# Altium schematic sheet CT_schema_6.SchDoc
size 371 x 336 mm
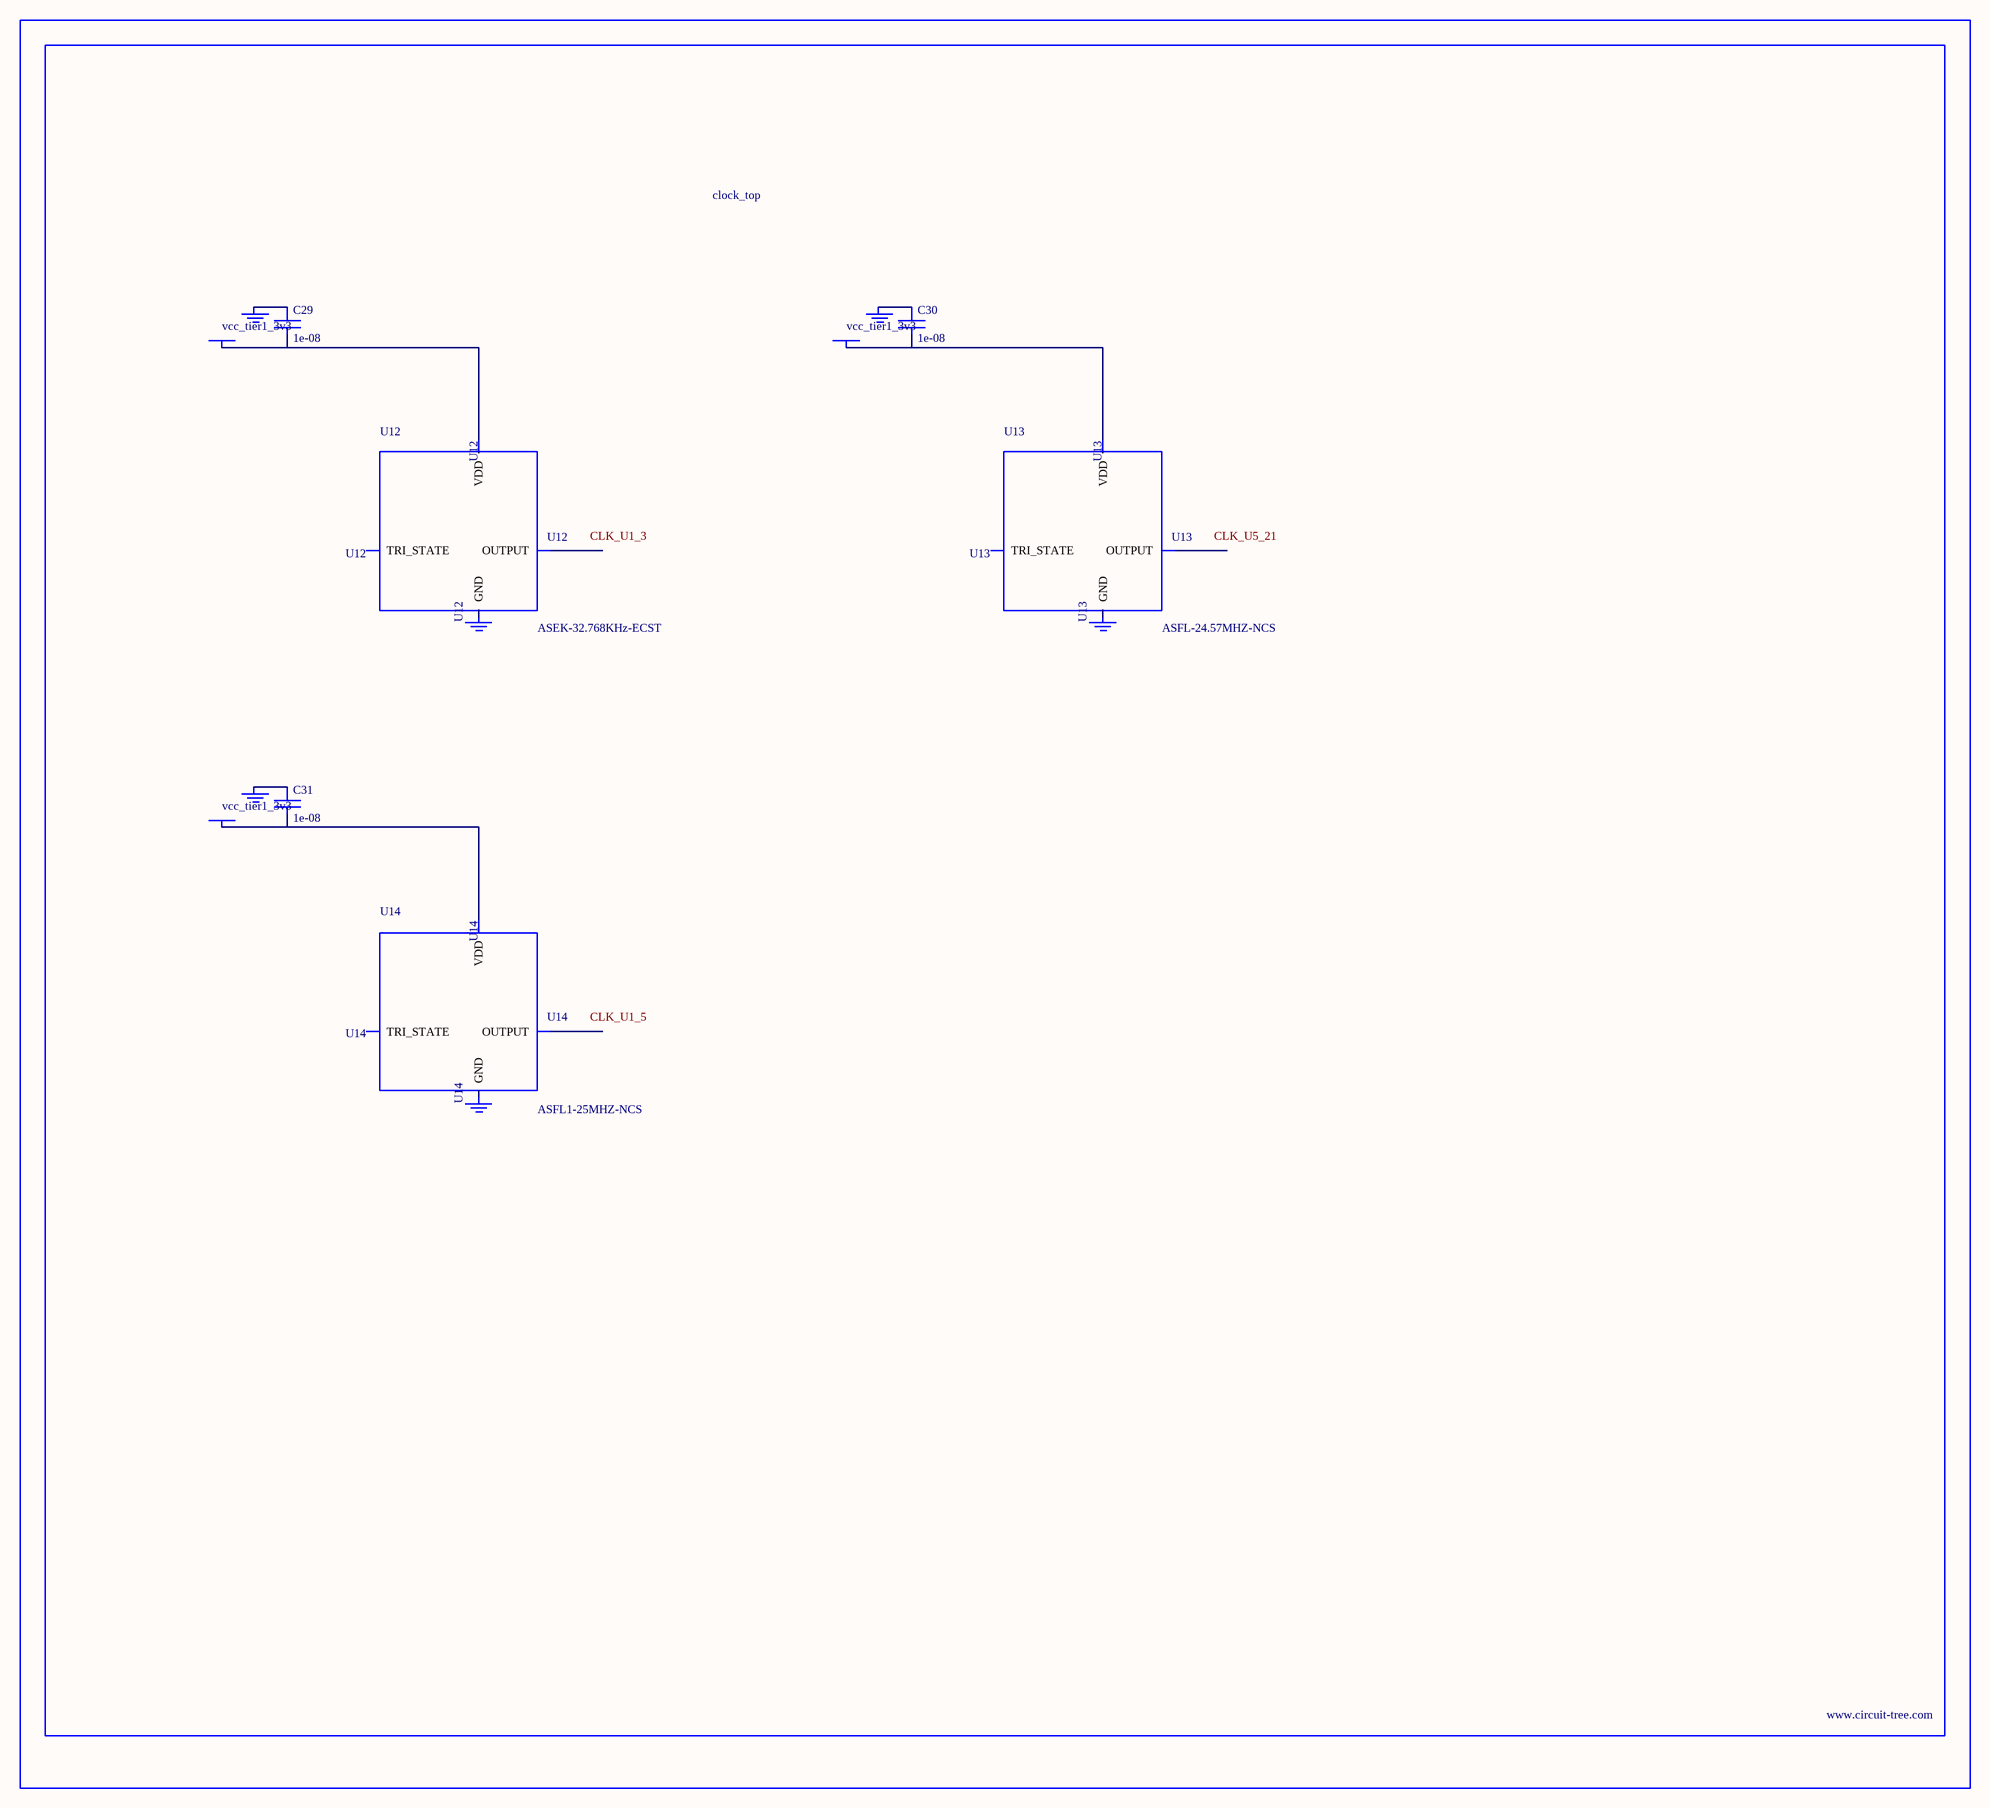
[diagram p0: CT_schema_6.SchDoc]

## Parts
BORDER5  (no value)
C29  1e-08  [C0402]
C30  1e-08  [C0402]
C31  1e-08  [C0402]
GND_INSTANCE_5_0  (no value)
GND_INSTANCE_5_1  (no value)
GND_INSTANCE_5_2  (no value)
GND_INSTANCE_5_3  (no value)
GND_INSTANCE_5_4  (no value)
GND_INSTANCE_5_5  (no value)
POWER_INSTANCE_5_0  vcc_tier1_3v3
POWER_INSTANCE_5_1  vcc_tier1_3v3
POWER_INSTANCE_5_2  vcc_tier1_3v3
U12  ASEK-32.768KHz-ECST  [ASEK]
U13  ASFL-24.57MHZ-NCS  [ASFL1]
U14  ASFL1-25MHZ-NCS  [ASFL1]

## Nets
NetC29_1: C29.1 GND_INSTANCE_5_0.0(GND)
NetC29_2: C29.2 POWER_INSTANCE_5_0.0(PWR) U12.4(VDD)
NetC30_1: C30.1 GND_INSTANCE_5_2.0(GND)
NetC30_2: C30.2 POWER_INSTANCE_5_1.0(PWR) U13.4(VDD)
NetC31_1: C31.1 GND_INSTANCE_5_4.0(GND)
NetC31_2: C31.2 POWER_INSTANCE_5_2.0(PWR) U14.4(VDD)

Not connected (* = marked no-connect by the designer): GND_INSTANCE_5_1 0(GND); GND_INSTANCE_5_3 0(GND); GND_INSTANCE_5_5 0(GND); U12 1(TRI_STATE) 2(GND) 3(OUTPUT); U13 1(TRI_STATE) 2(GND) 3(OUTPUT); U14 1(TRI_STATE) 2(GND) 3(OUTPUT)

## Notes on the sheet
- Labels drawn without touching a wire or pin: CLK_U1_3, CLK_U1_5, CLK_U5_21

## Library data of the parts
BORDER5 = BORDER_PAGE5
C29-C31 = C0402C103K3RAC
GND_INSTANCE_5_0-GND_INSTANCE_5_5 = GND
POWER_INSTANCE_5_0-POWER_INSTANCE_5_2 = PWR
